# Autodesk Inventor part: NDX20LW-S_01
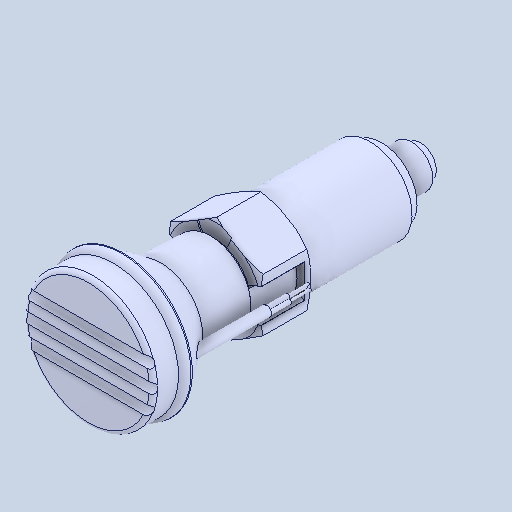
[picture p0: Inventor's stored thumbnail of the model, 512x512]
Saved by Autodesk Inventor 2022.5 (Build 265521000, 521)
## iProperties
Created: 2024-05
Part Number: NDX20LW-S_01
Material: 一般
Document SubType Name: Modeling
Designer: ImaoCorp
Density: 1 g/cm^3
Appearance: 既定
Author: ImaoCorp
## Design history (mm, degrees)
feature "NDX20LW-S_01"
node "ソリッド1"
